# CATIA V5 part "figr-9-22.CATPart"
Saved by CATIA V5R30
Part number: Part3
Bounding box of the stored display mesh (mm): x -112 to 0, y -101.683 to 103.294, z -80.304 to 44.415
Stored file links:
  D:\PROJECTS\CATIA V56R 2020\Resources\Parts File\c09_catia_v5_6r2020_prt\figr-9-22.CATPart
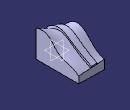
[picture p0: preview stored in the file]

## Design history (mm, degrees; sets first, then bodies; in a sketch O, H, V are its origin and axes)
Set1
  Plane1: type Offset, RefPlane yz-plane, Offset -112
  Plane2: type Offset, RefPlane yz-plane, Offset -63
  Plane3: type Normal, Curve Sketch4, RefPoint vertex of Sketch4
Body1 (main body)
  Sketch1 on yz-plane, origin (0, 0, 0), H (0, 1, 0), V (0, 0, 1)
    spline S1 through (-92.6897, 40.1119) (-30, 30) (10, -10) (60, -30) (97.3103, -50.3041)
    line L1 (97.3103, -50.3041) -> (97.3103, -80.3041)
    line L2 (97.3103, -80.3041) -> (-92.6897, -80.3041)
    line L3 (-92.6897, -80.3041) -> (-92.6897, 40.1119)
    point P3 (-92.6897, 40.1119)
    point P4 (97.3103, -50.3041)
    point P5 (-92.6897, 40.1119)
    point P6 (97.3103, -50.3041)
    vertical: L1 V, L3 V
    horizontal: L2 H
    coincidence: P5 P3, P6 P4
  Sketch2 on Plane1, origin (-112, 0, 0), H (0, 1, 0), V (0, 0, 1)
    spline S1 through (-90, -30) (-70, 10) (-20, 40) (40, 0) (100, -40)
    line L1 (100, -40) -> (100, -80)
    line L2 (100, -80) -> (-90, -80)
    line L3 (-90, -80) -> (-90, -30)
    point P3 (-90, -30)
    point P4 (100, -40)
    point P5 (40, 0)
    point P6 (-90, -30)
    point P7 (100, -40)
    coincidence: P5 H, P6 P3, P7 P4
    vertical: L1 V, L3 V
    horizontal: L2 H
  Loft1: Sections (Sketch1; Sketch2)
  Sketch3 on Plane3, origin (0, -40.1726, -44.9298), H (1, 0, 0), V (0, -0.7455, 0.6665)
    point P1 (-63, 68.4187)
    line L1 (-63, 68.4187) -> (-75.2117, 62.4925)
    line L2 (-75.2117, 62.4925) -> (-79.6266, 71.5898)
    line L3 (-79.6266, 71.5898) -> (-57.1205, 82.5119)
    line L4 (-57.1205, 82.5119) -> (-52.7056, 73.4145)
    point P5 (-52.7056, 73.4145)
    line L5 (-52.7056, 73.4145) -> (-63, 68.4187)
    reference projected point E1 (-63, 68.4187) from vertex of Sketch4
    perpendicularity: L2 L1
    parallelism: L3 L1, L4 L2, L5 L1
    coincidence: P5 L1, P1 E1
  Sketch4 on Plane2, origin (-63, 0, 0), H (0, 1, 0), V (0, 0, 1)
    intersected curve E1 from face of Loft1
  Rib1: profile Sketch3, centre curve Sketch4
